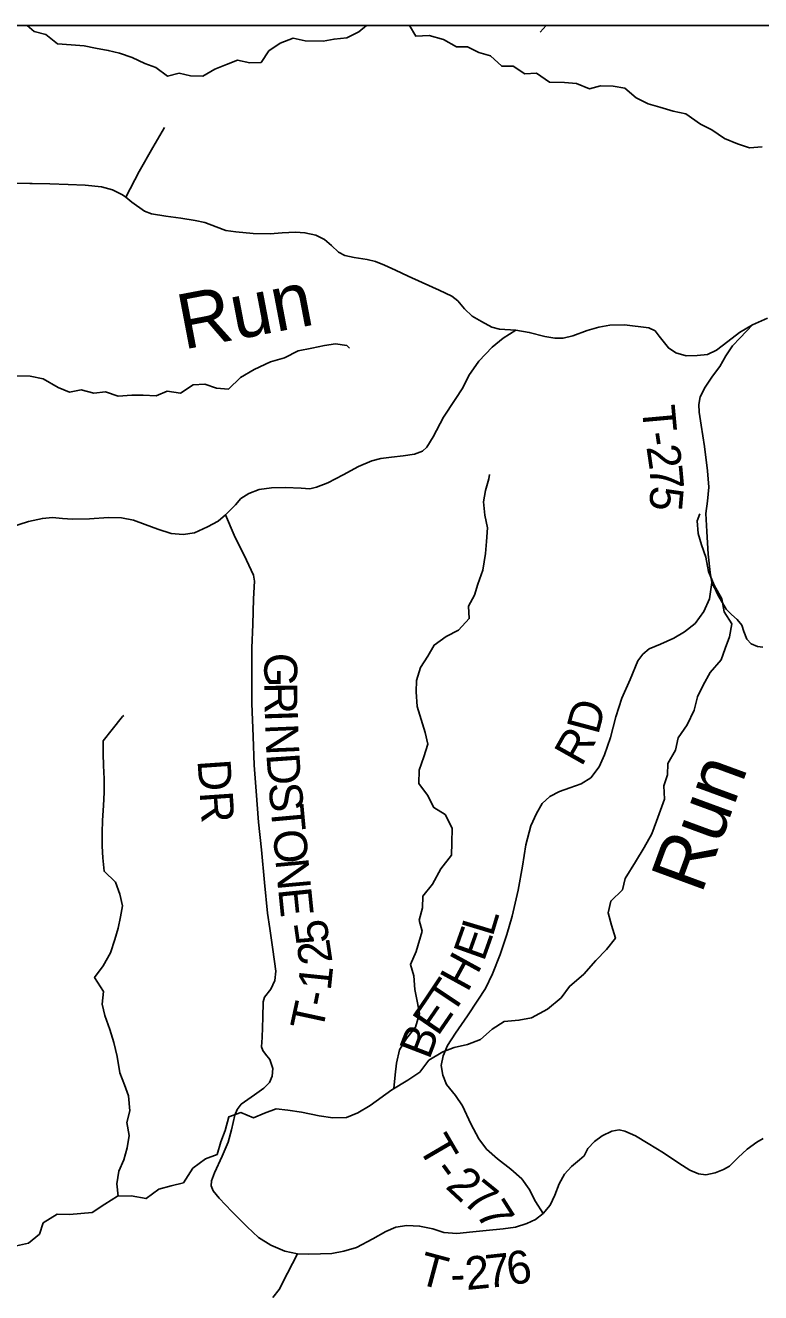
# Model space of a CAD drawing. Extents: x -84548 to 2262448, y -162180 to 525962.
# Drawn here: x 42517 to 49199, y 159360 to 170872 of the extents above; entities that cross this region are included whole.
import ezdxf

# ---------------------------------------------------------------- set-up
doc = ezdxf.new("R2010")
doc.units = 0
for name, color, linetype in [('GM_X_County', 7, 'Continuous'), ('GM_X_Minor_Lake', 7, 'Continuous'), ('GM_X_Minor_River_Text', 7, 'Continuous'), ('GM_X_State_Route', 7, 'Continuous'), ('GM_X_Township_Road', 7, 'Continuous'), ('GM_X_Township_Road_Text', 7, 'Continuous'), ('GM_X_Township_ROW', 7, 'Continuous'), ('GM_X_Unincorporated_Text', 7, 'Continuous')]:
    doc.layers.add(name, color=color, linetype=linetype)

msp = doc.modelspace()

# ---------------------------------------------------------------- linework, layer by layer
at = {"layer": 'GM_X_County'}
msp.add_line((31945, 170872), (67849, 170872), dxfattribs=at)
at = {"layer": 'GM_X_Minor_Lake'}
for points in [[(42427, 169439), (42557, 169436), (42578, 169435)], [(42578, 169435), (42578, 169435), (42741, 169433), (42907, 169427), (43061, 169422), (43210, 169405), (43310, 169378), (43399, 169334), (43429, 169311), (43486, 169266), (43600, 169184), (43664, 169159), (43793, 169140), (43929, 169122), (44059, 169099), (44148, 169081), (44250, 169041), (44339, 169010), (44429, 168998), (44587, 168983), (44743, 168980), (44851, 168989), (44973, 168995), (45057, 168989), (45156, 168967), (45236, 168926), (45299, 168871), (45363, 168811), (45421, 168782), (45505, 168765), (45622, 168746), (45700, 168727), (45781, 168693), (45882, 168649), (45997, 168595), (46122, 168537), (46279, 168468), (46394, 168413), (46447, 168369), (46508, 168297), (46578, 168230), (46661, 168181), (46756, 168131), (46826, 168113), (46973, 168103)], [(44991, 159713), (44875, 159738), (44749, 159790), (44637, 159862), (44532, 159957), (44394, 160097), (44277, 160219), (44223, 160284), (44206, 160330), (44210, 160377), (44236, 160449), (44307, 160599), (44360, 160728), (44390, 160838), (44421, 160971), (44443, 161023), (44478, 161071), (44598, 161158), (44684, 161218), (44735, 161268), (44761, 161327), (44765, 161397), (44738, 161477), (44700, 161525), (44674, 161559), (44664, 161593), (44669, 161679), (44674, 161859), (44679, 162002), (44689, 162044), (44747, 162118), (44784, 162196), (44792, 162281), (44767, 162477), (44738, 162667), (44719, 162807), (44690, 163087), (44662, 163382), (44637, 163634), (44614, 163917), (44596, 164151), (44587, 164411), (44575, 164712), (44574, 164946), (44575, 165217), (44584, 165431), (44589, 165662), (44598, 165822), (44589, 165878), (44527, 166014), (44416, 166242), (44335, 166426)], [(47224, 160080), (47153, 160187), (47097, 160301), (47028, 160393), (46930, 160481), (46808, 160577), (46709, 160664), (46637, 160756), (46566, 160894), (46491, 161058), (46425, 161150), (46344, 161250), (46310, 161336), (46295, 161424), (46313, 161510), (46353, 161606), (46426, 161717), (46535, 161874), (46630, 162016), (46698, 162123), (46763, 162257), (46832, 162432), (46893, 162612), (46942, 162779), (46997, 163016), (47036, 163234), (47065, 163427), (47112, 163601), (47161, 163712), (47215, 163804), (47284, 163866), (47370, 163911), (47464, 163945), (47569, 163982), (47655, 164038), (47733, 164137), (47780, 164245), (47835, 164404), (47884, 164592), (47939, 164759), (48014, 164930), (48083, 165100), (48129, 165160), (48187, 165207), (48288, 165251), (48410, 165306), (48508, 165363), (48605, 165439), (48683, 165548), (48734, 165664), (48757, 165810)], [(49221, 160760), (49165, 160727), (49076, 160663), (48996, 160588), (48915, 160510), (48861, 160478), (48785, 160447), (48701, 160431), (48635, 160440), (48557, 160474), (48457, 160536), (48316, 160629), (48178, 160715), (48062, 160783), (47964, 160826), (47912, 160838), (47846, 160826), (47758, 160785), (47688, 160733), (47629, 160670), (47595, 160604), (47553, 160566), (47480, 160505), (47416, 160435), (47368, 160347), (47329, 160244), (47286, 160156), (47224, 160080)], [(47224, 160080), (47152, 160025), (47073, 159987), (46971, 159956), (46859, 159940), (46705, 159925), (46583, 159912), (46439, 159896), (46319, 159905), (46221, 159939), (46099, 159964), (45985, 159970), (45885, 159955), (45794, 159915), (45674, 159850), (45525, 159771), (45411, 159737), (45303, 159716), (45199, 159712), (45091, 159709), (44991, 159713)], [(44765, 159317), (44825, 159388), (44898, 159536), (44991, 159713)]]:
    msp.add_lwpolyline(points, dxfattribs=at)
at = {"layer": 'GM_X_Minor_River_Text'}
msp.add_lwpolyline([(42375, 166311), (42546, 166364), (42672, 166394), (42764, 166403), (42856, 166393), (42946, 166386), (43100, 166390), (43274, 166401), (43390, 166398), (43500, 166376), (43606, 166338), (43720, 166297), (43842, 166255), (43952, 166248), (44054, 166262), (44173, 166317), (44269, 166367), (44335, 166426), (44428, 166516), (44476, 166575), (44548, 166619), (44643, 166656), (44755, 166672), (44881, 166673), (45023, 166667), (45103, 166662), (45163, 166676), (45265, 166716), (45404, 166789), (45546, 166864), (45666, 166917), (45747, 166937), (45843, 166949), (45951, 166962), (46055, 166978), (46125, 167005), (46167, 167039), (46224, 167135), (46317, 167314), (46424, 167475), (46492, 167581), (46547, 167692), (46638, 167823), (46760, 167949), (46859, 168030), (46973, 168103), (47097, 168083), (47239, 168046), (47329, 168032), (47405, 168032), (47493, 168053), (47624, 168101), (47728, 168132), (47830, 168150), (47962, 168151), (48184, 168124), (48240, 168098), (48278, 168050), (48361, 167942), (48427, 167897), (48521, 167871), (48623, 167874), (48715, 167882), (48799, 167922), (48902, 168001), (49008, 168082), (49125, 168152), (49261, 168213)], dxfattribs=at)
at = {"layer": 'GM_X_State_Route'}
for points in [[(42535, 170872), (42596, 170816), (42702, 170788), (42809, 170706), (42933, 170694), (43052, 170686), (43154, 170666), (43271, 170644), (43374, 170621), (43488, 170579), (43603, 170525), (43703, 170489), (43808, 170411), (43914, 170437), (44019, 170415), (44129, 170411), (44238, 170473), (44344, 170517), (44445, 170555), (44558, 170531), (44660, 170535), (44730, 170640), (44833, 170712), (44950, 170756), (45060, 170732), (45223, 170730), (45323, 170748), (45438, 170758), (45547, 170814), (45617, 170872)], [(46007, 170872), (46067, 170774), (46186, 170780), (46317, 170744), (46435, 170676), (46536, 170676), (46638, 170626), (46743, 170595), (46847, 170501), (46950, 170501), (47056, 170433), (47161, 170439), (47279, 170355), (47418, 170353), (47525, 170345), (47643, 170295), (47744, 170323), (47860, 170319), (47965, 170303), (48067, 170215), (48176, 170158), (48282, 170128), (48405, 170094), (48520, 170070), (48652, 169976), (48757, 169922), (48871, 169846), (48988, 169796), (49097, 169760), (49213, 169770)], [(42438, 167689), (42561, 167685), (42678, 167661), (42816, 167582), (42917, 167540), (43025, 167562), (43140, 167530), (43244, 167544), (43361, 167504), (43486, 167512), (43588, 167514), (43705, 167506), (43807, 167548), (43928, 167530), (44042, 167608), (44147, 167612), (44254, 167576), (44362, 167566), (44473, 167673), (44597, 167745), (44746, 167815), (44871, 167853), (44997, 167915), (45120, 167939), (45235, 167963), (45337, 167979), (45440, 167963), (45462, 167939)], [(45865, 161213), (45878, 161338), (45890, 161446), (45916, 161566), (45980, 161670), (46062, 161773), (46099, 161897), (46079, 162007), (46058, 162113), (46046, 162238), (46016, 162342), (46068, 162458), (46123, 162643), (46095, 162743), (46125, 162855), (46129, 162961), (46217, 163070), (46294, 163210), (46390, 163334), (46394, 163445), (46396, 163579), (46332, 163703), (46229, 163767), (46173, 163878), (46093, 163986), (46095, 164106), (46139, 164226), (46175, 164341), (46151, 164447), (46115, 164567), (46077, 164685), (46069, 164818), (46071, 164922), (46107, 165038), (46175, 165143), (46233, 165243), (46342, 165321), (46452, 165377), (46551, 165483), (46543, 165596), (46599, 165696), (46629, 165796), (46674, 165924), (46700, 166075), (46708, 166183), (46716, 166309), (46692, 166422), (46680, 166544), (46698, 166646), (46730, 166754), (46736, 166792)], [(42436, 159784), (42545, 159808), (42647, 159892), (42679, 159994), (42806, 160073), (42919, 160069), (43124, 160087), (43240, 160165), (43353, 160237), (43479, 160239), (43614, 160215), (43729, 160301), (43841, 160331), (43954, 160357), (44038, 160490), (44153, 160574), (44259, 160616), (44293, 160730), (44334, 160832), (44366, 160957), (44476, 160995), (44589, 160947), (44691, 160989), (44796, 161031), (44901, 161019), (45027, 160999), (45188, 160967), (45311, 160947), (45435, 160951), (45540, 160993), (45652, 161061), (45849, 161203), (45992, 161291), (46103, 161364), (46185, 161472), (46312, 161548), (46414, 161586), (46535, 161614), (46653, 161660), (46760, 161753), (46869, 161823), (47003, 161835), (47116, 161855), (47261, 161935), (47387, 162039), (47462, 162142), (47592, 162254), (47701, 162376), (47799, 162476), (47880, 162579), (47843, 162697), (47813, 162811), (47837, 162917), (47944, 163020), (47968, 163122), (48063, 163274), (48141, 163404), (48211, 163527), (48254, 163643), (48290, 163743), (48324, 163844), (48318, 163964), (48354, 164064), (48356, 164168), (48426, 164289), (48451, 164399), (48531, 164517), (48595, 164651), (48625, 164772), (48676, 164878), (48740, 164992), (48839, 165109), (48877, 165211), (48915, 165317), (48937, 165435), (48869, 165546), (48847, 165664), (48776, 165786), (48724, 165910), (48700, 166041), (48662, 166153), (48632, 166255), (48622, 166371), (48646, 166434)], [(43361, 160237), (43349, 160349), (43367, 160462), (43413, 160566), (43443, 160674), (43459, 160788), (43439, 160907), (43467, 161013), (43453, 161147), (43417, 161249), (43375, 161358), (43351, 161506), (43321, 161632), (43286, 161751), (43238, 161877), (43214, 161981), (43228, 162095), (43146, 162224), (43224, 162328), (43292, 162446), (43331, 162569), (43361, 162671), (43383, 162775), (43399, 162875), (43375, 162979), (43337, 163088), (43232, 163188), (43222, 163310), (43216, 163415), (43216, 163541), (43218, 163649), (43226, 163785), (43234, 163902), (43234, 164028), (43226, 164148), (43224, 164256), (43224, 164373), (43306, 164477), (43399, 164593), (43413, 164603)]]:
    msp.add_lwpolyline(points, dxfattribs=at)
at = {"layer": 'GM_X_Township_Road_Text'}
for points in [[(49125, 168152), (49014, 168034), (48944, 167961), (48883, 167869), (48829, 167772), (48762, 167686), (48696, 167587), (48651, 167499), (48637, 167427), (48640, 167359), (48658, 167241), (48689, 167048), (48716, 166824), (48727, 166676), (48716, 166550), (48702, 166439), (48711, 166275), (48722, 166069), (48741, 165903), (48757, 165810), (48778, 165767), (48779, 165765)], [(48779, 165765), (48810, 165698), (48886, 165569), (48933, 165519), (48985, 165475), (49027, 165423), (49047, 165365), (49074, 165297), (49114, 165255), (49172, 165231), (49218, 165225)]]:
    msp.add_lwpolyline(points, dxfattribs=at)
at = {"layer": 'GM_X_Township_ROW'}
msp.add_line((47197, 170812), (47249, 170872), dxfattribs=at)
msp.add_lwpolyline([(43429, 169311), (43551, 169546), (43676, 169764), (43782, 169945)], dxfattribs=at)

# ---------------------------------------------------------------- texts
at = {"layer": 'GM_X_Township_Road'}
for s, rotation, p in [('T', 275.1496, (48119, 167409)), ('-', 278.586, (48142, 167166)), ('2', 278.4087, (48160, 167044)), ('7', 275.279, (48186, 166865)), ('5', 265.1179, (48203, 166696)), ('G', 270.0328, (44688, 165172)), ('R', 270.7203, (44688, 164904)), ('D', 75.0587, (47722, 164420)), ('I', 271.8675, (44692, 164651)), ('N', 272.3608, (44696, 164525)), ('R', 60.5485, (47571, 164130)), ('DR', 273.9488, (44081, 164195)), ('D', 274.0728, (44707, 164251)), ('S', 275.1649, (44726, 163982)), ('T', 275.2434, (44745, 163780)), ('O', 275.2443, (44765, 163556)), ('N', 275.248, (44789, 163293)), ('E', 275.8027, (44814, 163027)), ('L', 73.2395, (46763, 162586)), ('5', 97.9932, (45282, 162546)), ('E', 70.3871, (46683, 162360)), ('2', 98.6593, (45310, 162364)), ('H', 61.2751, (46535, 162081)), ('1', 84.0438, (45292, 162097)), ('T', 56.2811, (46396, 161871)), ('T', 77.8142, (45215, 161722)), ('-', 78.3918, (45263, 161944)), ('E', 55.5016, (46266, 161682)), ('B', 68.9618, (46187, 161469)), ('T', 300.3493, (46080, 160684)), ('-', 305.9949, (46211, 160464)), ('2', 317.2467, (46326, 160316)), ('7', 320.944, (46478, 160177)), ('7', 302.365, (46604, 160079)), ('T', 344.9721, (46070, 159445)), ('2', 5.7182, (46527, 159383)), ('7', 6.2125, (46714, 159401)), ('6', 9.2907, (46915, 159424)), ('-', 2.5878, (46386, 159376))]:
    msp.add_text(s, height=300, rotation=rotation, dxfattribs=at).set_placement(p)
at = {"layer": 'GM_X_Unincorporated_Text'}
for rotation, p in [(10.8099, (43954, 167926)), (69.8105, (48661, 162972))]:
    msp.add_text('Run', height=500, rotation=rotation, dxfattribs=at).set_placement(p)

doc.saveas('drawing.dxf')
